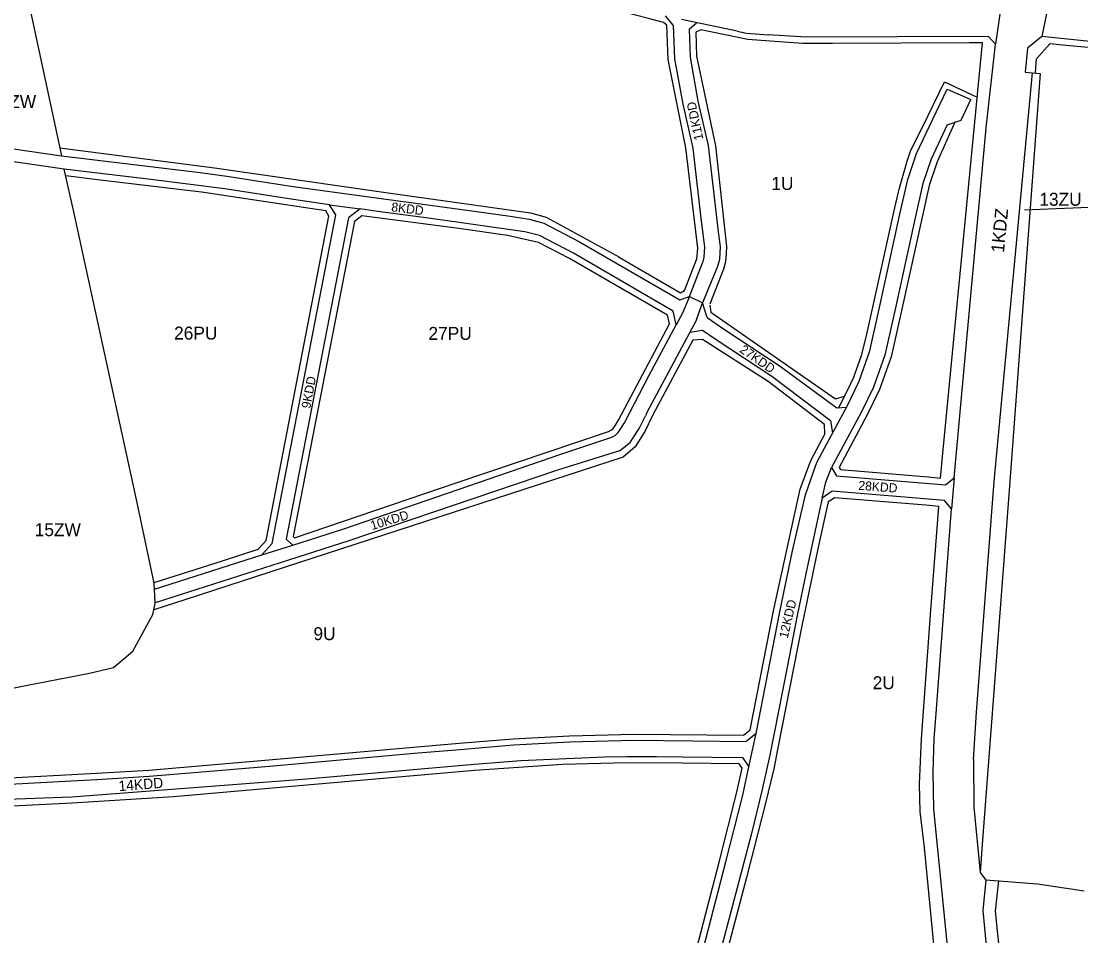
# Model space of a CAD drawing. Extents: x 7428203 to 7432868, y 5542672 to 5545406.
# Drawn here: x 7430602 to 7431420, y 5543859 to 5544564 of the extents above; entities that cross this region are included whole.
import ezdxf

# ---------------------------------------------------------------- set-up
doc = ezdxf.new("R2010")
doc.units = 0
for name, color, linetype in [('linie_rozgraniczajace', 7, 'Continuous'), ('linie_zabudowy_nieprzekraczalne', 7, 'Continuous'), ('oznaczenia_przeznaczen', 7, 'Continuous')]:
    doc.layers.add(name, color=color, linetype=linetype)

msp = doc.modelspace()

# ---------------------------------------------------------------- linework, layer by layer
at = {"layer": 'linie_rozgraniczajace'}
for p, q in [((7430604.98, 5544592.38), (7430633.38, 5544460.3)), ((7431397.08, 5544588.16), (7431389.69, 5544552.15)), ((7431105.3, 5544561.03), (7431099.31, 5544568.13)), ((7431154.56, 5544556.24), (7431111.57, 5544565.22)), ((7431357.47, 5544571.25), (7431353.84, 5544546.3)), ((7431117.44, 5544557.87), (7431123.24, 5544562.78)), ((7431154.56, 5544556.24), (7431161.78, 5544554.73)), ((7431161.78, 5544554.73), (7431178.45, 5544553.62)), ((7431207.83, 5544551.66), (7431178.45, 5544553.62)), ((7431348.46, 5544552.28), (7431207.83, 5544551.66)), ((7431353.84, 5544546.3), (7431348.46, 5544552.28)), ((7431389.69, 5544552.15), (7431378.65, 5544543.23)), ((7431346.8, 5544481.9), (7431353.84, 5544546.3)), ((7431378.65, 5544543.23), (7431376.85, 5544524.65)), ((7431388.4, 5544523.8), (7431364.07, 5544198.77)), ((7431376.85, 5544524.65), (7431388.4, 5544523.8)), ((7431305.61, 5544488.59), (7431316.53, 5544511.55)), ((7431316.53, 5544511.55), (7431334.86, 5544503.54)), ((7431327.38, 5544487.8), (7431334.86, 5544503.54)), ((7431292.99, 5544462.02), (7431305.61, 5544488.59)), ((7431316.72, 5544484.01), (7431304.14, 5544457.54)), ((7431316.72, 5544484.01), (7431327.38, 5544487.8)), ((7431321.92, 5544211.85), (7431346.8, 5544481.9)), ((7430635.44, 5544449.92), (7430571.27, 5544459.14)), ((7431286.32, 5544441.98), (7431292.99, 5544462.02)), ((7430642.68, 5544416.89), (7430635.44, 5544449.92)), ((7431304.14, 5544457.54), (7431297.89, 5544438.74)), ((7431280.12, 5544415.08), (7431286.32, 5544441.98)), ((7431297.89, 5544438.74), (7431291.83, 5544412.46)), ((7430840.14, 5544422.46), (7430863.59, 5544419.22)), ((7430691.42, 5544193.97), (7430642.68, 5544416.89)), ((7431264.97, 5544345.58), (7431280.12, 5544415.08)), ((7431291.83, 5544412.46), (7431276.68, 5544342.95)), ((7431117.86, 5544351.65), (7431127.83, 5544377.61)), ((7431139.48, 5544374.73), (7431127.74, 5544346.69)), ((7431117.86, 5544351.65), (7431127.74, 5544346.69)), ((7431123.16, 5544333.64), (7431127.74, 5544346.69)), ((7431131.44, 5544335.49), (7431127.74, 5544346.69)), ((7431256.96, 5544309.86), (7431264.97, 5544345.58)), ((7431276.68, 5544342.95), (7431268.51, 5544306.54)), ((7431123.16, 5544333.64), (7431105.78, 5544301.14)), ((7431118.1, 5544324.18), (7431127.79, 5544325.85)), ((7431248.71, 5544286.44), (7431256.96, 5544309.86)), ((7431268.51, 5544306.54), (7431259.81, 5544281.82)), ((7431105.78, 5544301.14), (7431084.94, 5544262.17)), ((7431239.85, 5544268.13), (7431248.71, 5544286.44)), ((7431259.81, 5544281.82), (7431250.54, 5544262.67)), ((7431084.94, 5544262.17), (7431083.75, 5544259.73)), ((7431216.47, 5544224.65), (7431239.85, 5544268.13)), ((7431250.54, 5544262.67), (7431227.46, 5544219.73)), ((7431231.49, 5544265.75), (7431238.91, 5544266.38)), ((7431226.58, 5544256.09), (7431228.16, 5544246.39)), ((7431063.91, 5544232.54), (7431015.88, 5544217.76)), ((7431207.33, 5544198.74), (7431215.19, 5544221.63)), ((7431215.19, 5544221.63), (7431216.47, 5544224.65)), ((7431015.88, 5544217.76), (7430854.88, 5544163.28)), ((7431227.46, 5544219.73), (7431231.25, 5544213.4)), ((7431231.25, 5544213.4), (7431315.39, 5544206.37)), ((7431315.39, 5544206.37), (7431321.92, 5544211.85)), ((7431321.92, 5544211.85), (7431320.03, 5544187.92)), ((7431197.34, 5544155.42), (7431207.33, 5544198.74)), ((7431227.87, 5544201.64), (7431220.21, 5544196.26)), ((7431314.5, 5544194.41), (7431227.87, 5544201.64)), ((7431364.07, 5544198.77), (7431343.44, 5543925.8)), ((7430704.81, 5544130.56), (7430691.42, 5544193.97)), ((7431220.21, 5544196.26), (7431218.27, 5544187.95)), ((7431320.03, 5544187.92), (7431314.5, 5544194.41)), ((7431218.27, 5544187.95), (7431207.89, 5544139.2)), ((7431308.16, 5544030.14), (7431320.03, 5544187.92)), ((7430787.97, 5544152.39), (7430811.85, 5544160.02)), ((7430854.88, 5544163.28), (7430814.89, 5544150.5)), ((7430814.89, 5544150.5), (7430705.48, 5544115.51)), ((7431187.53, 5544108.38), (7431197.34, 5544155.42)), ((7431207.89, 5544139.2), (7431200.76, 5544105.73)), ((7430705.02, 5544125.87), (7430704.81, 5544130.56)), ((7430705.48, 5544115.51), (7430705.02, 5544125.87)), ((7430703.65, 5544106.55), (7430705.51, 5544114.87)), ((7430705.51, 5544114.87), (7430705.48, 5544115.51)), ((7430688.24, 5544078.05), (7430703.65, 5544106.55)), ((7431169.21, 5544014.62), (7431187.53, 5544108.38)), ((7431200.76, 5544105.73), (7431193.28, 5544065.85)), ((7430673.38, 5544065.63), (7430688.24, 5544078.05)), ((7430654.86, 5544061.19), (7430673.38, 5544065.63)), ((7431193.28, 5544065.85), (7431179.84, 5543998.02)), ((7430607.17, 5544051.99), (7430654.86, 5544061.19)), ((7430510.83, 5544032.94), (7430607.17, 5544051.99)), ((7431306.69, 5544010.57), (7431308.16, 5544030.14)), ((7431336.87, 5543994.72), (7431339.31, 5544031)), ((7431074.8, 5544009.15), (7431025.49, 5544007.96)), ((7431120.26, 5544008.69), (7431074.8, 5544009.15)), ((7431161.3, 5544008.34), (7431120.26, 5544008.69)), ((7431169.21, 5544014.62), (7431161.3, 5544008.34)), ((7431163.66, 5543988.83), (7431169.21, 5544014.62)), ((7430940.49, 5544002.16), (7430905.41, 5543999.22)), ((7430982.03, 5544005.63), (7430940.49, 5544002.16)), ((7431025.49, 5544007.96), (7430982.03, 5544005.63)), ((7430876.98, 5543996.76), (7430793.67, 5543989.27)), ((7430905.41, 5543999.22), (7430876.98, 5543996.76)), ((7430951.57, 5543991.04), (7430987.68, 5543993.92)), ((7430987.68, 5543993.92), (7431052.25, 5543996.61)), ((7431052.25, 5543996.61), (7431069.66, 5543997.03)), ((7431069.66, 5543997.03), (7431092.3, 5543996.97)), ((7431092.3, 5543996.97), (7431112.27, 5543996.77)), ((7431112.27, 5543996.77), (7431158.71, 5543996.18)), ((7431158.71, 5543996.18), (7431163.66, 5543988.83)), ((7431179.84, 5543998.02), (7431173.73, 5543970.49)), ((7430735.33, 5543984.35), (7430700.98, 5543981.37)), ((7430793.67, 5543989.27), (7430735.33, 5543984.35)), ((7430822.44, 5543979.62), (7430951.57, 5543991.04)), ((7430631.1, 5543977.3), (7430578.76, 5543974.63)), ((7430660.59, 5543978.99), (7430631.1, 5543977.3)), ((7430641.3, 5543965.87), (7430822.44, 5543979.62)), ((7430700.98, 5543981.37), (7430660.59, 5543978.99)), ((7431173.73, 5543970.49), (7431165.55, 5543937.59)), ((7430447, 5543958.42), (7430641.3, 5543965.87)), ((7431165.55, 5543937.59), (7431123.36, 5543776.97)), ((7431343.44, 5543925.8), (7431342.05, 5543907.45)), ((7431386.19, 5543898.41), (7431346.33, 5543901.64)), ((7431422.33, 5543893.08), (7431386.19, 5543898.41))]:
    msp.add_line(p, q, dxfattribs=at)
for points in [[(7431105.3, 5544561.03), (7431106.35, 5544535.11), (7431112.57, 5544499.95), (7431120.29, 5544466.13), (7431123.22, 5544441.19), (7431126.91, 5544409.92), (7431128.31, 5544398.07), (7431129.4, 5544389.65), (7431128.94, 5544382.08), (7431127.83, 5544377.61)], [(7431117.44, 5544557.87), (7431118.31, 5544536.4), (7431124.33, 5544502.33), (7431132.13, 5544468.17), (7431140.22, 5544399.55), (7431141.45, 5544390.06), (7431140.85, 5544380.26), (7431139.48, 5544374.73)], [(7431654.46, 5543877.07), (7431672.85, 5544147.41), (7431697.38, 5544505.35), (7431680.1, 5544526.46), (7431451.66, 5544545.79), (7431389.69, 5544552.15)], [(7431339.31, 5544031), (7431352.78, 5544209), (7431382.53, 5544524.23)], [(7430569.42, 5544469.51), (7430633.38, 5544460.3), (7430740.24, 5544447.34), (7430760.86, 5544444.53), (7430811.92, 5544436.53), (7430957.31, 5544416.86), (7430981.37, 5544413.37), (7430994.17, 5544411.27), (7431005.45, 5544408.24), (7431033.05, 5544393.91), (7431110.24, 5544349.14), (7431117.86, 5544351.65), (7431112.34, 5544338.85), (7431107.55, 5544329.89), (7431105.22, 5544340.49), (7431028.24, 5544385.14), (7431002.04, 5544398.75), (7430990.73, 5544401.69), (7430916.34, 5544412.18), (7430877.04, 5544417.36), (7430863.59, 5544419.22), (7430854.75, 5544412.37), (7430806.64, 5544164.65), (7430811.85, 5544160.02), (7430851.76, 5544172.78), (7431018.42, 5544230.14), (7431057, 5544242.92), (7431058.82, 5544243.72), (7431060.71, 5544244.78), (7431062.82, 5544246.81), (7431064.84, 5544249.88), (7431067.61, 5544254.32), (7431086.71, 5544290.93), (7431105.7, 5544326.44), (7431107.55, 5544329.89)], [(7430705.02, 5544125.87), (7430787.97, 5544152.39), (7430795.78, 5544161.19), (7430844.9, 5544414.72), (7430840.14, 5544422.46), (7430810.43, 5544426.64), (7430759.42, 5544434.64), (7430702.11, 5544441.87), (7430635.44, 5544449.92)], [(7431131.44, 5544335.49), (7431144, 5544326.77), (7431187.05, 5544298.43), (7431231.49, 5544265.75)], [(7431127.79, 5544325.85), (7431138.4, 5544318.48), (7431181.34, 5544290.23), (7431226.58, 5544256.09)], [(7431063.91, 5544232.54), (7431072.1, 5544239.08), (7431078.85, 5544249.93), (7431083.75, 5544259.73)], [(7431220.21, 5544196.26), (7431223.1, 5544208.59), (7431227.46, 5544219.73)], [(7431309.1, 5543927.71), (7431306.2, 5543956.49), (7431305.78, 5543984.85), (7431306.69, 5544010.57)], [(7431336.87, 5543994.72), (7431337.06, 5543957.82), (7431342.05, 5543907.45), (7431346.33, 5543901.64), (7431344.13, 5543878.23), (7431348.52, 5543831.97), (7431390, 5543702.36), (7431390.73, 5543691.85), (7431392.19, 5543663.75), (7431392.48, 5543658.26), (7431391.71, 5543646.79), (7431385.31, 5543618.42), (7431364, 5543513.86)], [(7431094.31, 5543717.17), (7431101.48, 5543744.76), (7431145.8, 5543915.56), (7431159, 5543967.17), (7431163.66, 5543988.83)], [(7431333.87, 5543519.93), (7431356.3, 5543627.18), (7431361.52, 5543652.65), (7431362.19, 5543670.59), (7431359.03, 5543701.57), (7431327.35, 5543799.07), (7431319.67, 5543822.68), (7431309.1, 5543927.71)]]:
    msp.add_lwpolyline(points, dxfattribs=at)
at = {"layer": 'linie_zabudowy_nieprzekraczalne'}
for p, q in [((7431205.18, 5544546.83), (7431180.04, 5544548.5)), ((7431228.25, 5544546.75), (7431205.18, 5544546.83)), ((7431333.82, 5544547.21), (7431228.25, 5544546.75)), ((7431301.82, 5544491.41), (7431314.42, 5544517.15)), ((7431314.42, 5544517.15), (7431339.84, 5544505.41)), ((7431288.34, 5544463.89), (7431301.82, 5544491.41)), ((7431322.86, 5544486.63), (7431308.79, 5544455.67)), ((7431285.73, 5544456.04), (7431288.34, 5544463.89)), ((7431279.46, 5544434.49), (7431285.73, 5544456.04)), ((7431308.79, 5544455.67), (7431302.7, 5544437.38)), ((7431275.38, 5544416.79), (7431279.46, 5544434.49)), ((7431302.7, 5544437.38), (7431281.56, 5544341.86)), ((7431261.42, 5544352.78), (7431275.38, 5544416.79)), ((7431254.17, 5544320.27), (7431261.42, 5544352.78)), ((7431281.56, 5544341.86), (7431273.33, 5544305.16)), ((7431250.39, 5544306.26), (7431254.17, 5544320.27)), ((7431120.46, 5544318), (7431089.35, 5544259.81)), ((7431245.59, 5544292.62), (7431250.39, 5544306.26)), ((7431273.33, 5544305.16), (7431264.43, 5544279.89)), ((7431241.97, 5544283.99), (7431243.41, 5544286.96)), ((7431243.41, 5544286.96), (7431244.24, 5544288.79)), ((7431244.24, 5544288.79), (7431245.59, 5544292.62)), ((7431232.7, 5544265.61), (7431240.37, 5544280.68)), ((7431240.37, 5544280.68), (7431241.97, 5544283.99)), ((7431264.43, 5544279.89), (7431254.99, 5544260.4)), ((7431254.99, 5544260.4), (7431233.2, 5544219.87)), ((7431211.29, 5544225.22), (7431222.42, 5544245.99)), ((7431066.55, 5544227.91), (7430729.33, 5544117.89)), ((7431203.16, 5544203.14), (7431211.29, 5544225.22)), ((7431233.2, 5544219.87), (7431234.22, 5544218.17)), ((7431234.22, 5544218.17), (7431301.89, 5544212.52)), ((7431182.62, 5544109.36), (7431203.16, 5544203.14)), ((7431229.98, 5544196.44), (7431224.69, 5544193.29)), ((7431300.19, 5544190.78), (7431229.98, 5544196.44)), ((7431224.69, 5544193.29), (7431216.82, 5544157.13)), ((7431216.82, 5544157.13), (7431204.35, 5544097.72)), ((7430729.33, 5544117.89), (7430704.41, 5544109.95)), ((7431164.7, 5544017.42), (7431182.62, 5544109.36)), ((7431204.35, 5544097.72), (7431186.02, 5544003.48)), ((7431159.57, 5544013.36), (7431164.7, 5544017.42)), ((7430940.07, 5544007.14), (7430981.69, 5544010.62)), ((7430981.69, 5544010.62), (7431025.3, 5544012.96)), ((7431025.3, 5544012.96), (7431074.76, 5544014.15)), ((7431074.76, 5544014.15), (7431159.57, 5544013.36)), ((7430793.23, 5543994.25), (7430940.07, 5544007.14)), ((7431186.02, 5544003.48), (7431182.85, 5543987.44)), ((7430700.62, 5543986.36), (7430793.23, 5543994.25)), ((7430578.52, 5543979.63), (7430660.3, 5543983.98)), ((7430660.3, 5543983.98), (7430700.62, 5543986.36)), ((7431182.85, 5543987.44), (7431176.27, 5543959.98)), ((7431176.27, 5543959.98), (7431161.79, 5543903.59)), ((7431161.79, 5543903.59), (7431133.34, 5543795.27))]:
    msp.add_line(p, q, dxfattribs=at)
for points in [[(7431097.8, 5544563.11), (7431085.02, 5544566.28), (7431068.04, 5544570.76), (7431053.43, 5544576.37), (7431004.01, 5544606.59), (7430904.7, 5544666.36), (7430892.77, 5544671.65), (7430881.52, 5544675.43), (7430857.73, 5544679.93), (7430843.46, 5544680.67), (7430820.83, 5544678.62), (7430803.18, 5544674.25), (7430797.44, 5544672.31), (7430606.82, 5544587.15)], [(7431063.14, 5544382.37), (7431110.81, 5544354.59), (7431113.93, 5544356.36), (7431123.48, 5544380.83), (7431124.35, 5544388.98), (7431114.91, 5544466.23), (7431101.37, 5544534.57), (7431100.3, 5544560.99), (7431097.8, 5544563.11)], [(7431180.04, 5544548.5), (7431162.91, 5544549.87), (7431126.42, 5544557.33), (7431122.79, 5544555.58), (7431123.29, 5544536.94), (7431137.91, 5544467.8), (7431146.47, 5544390.23), (7431146.14, 5544384.86), (7431145.52, 5544378.33), (7431144.09, 5544372.8), (7431133.54, 5544345.78)], [(7431301.89, 5544212.52), (7431311.45, 5544211.59), (7431313.56, 5544233.49), (7431323.58, 5544337.28), (7431343.89, 5544547.26), (7431333.82, 5544547.21)], [(7431408.5, 5544545.23), (7431395.74, 5544546.5), (7431385.32, 5544534.64), (7431384.5, 5544524.49)], [(7431649.47, 5543877.41), (7431655.88, 5543974.89), (7431665.17, 5544116.21), (7431681.81, 5544351.27), (7431692.14, 5544503.86), (7431677.57, 5544521.65), (7431530.62, 5544534.23), (7431408.5, 5544545.23)], [(7430632.12, 5544466.45), (7430751.23, 5544450.89), (7430885.33, 5544431.64), (7430995.22, 5544416.16), (7431007.27, 5544412.93), (7431063.68, 5544381.92)], [(7430704.72, 5544131.02), (7430757.56, 5544147.92), (7430785.14, 5544156.73), (7430791.13, 5544163.48), (7430839.62, 5544413.76), (7430837.12, 5544417.83), (7430825.21, 5544419.51), (7430741.33, 5544432.05), (7430661.14, 5544441.78), (7430636.57, 5544444.75)], [(7431133.57, 5544344.91), (7431134.3, 5544339.6), (7431230.4, 5544272.69), (7431237.42, 5544274.88)], [(7431222.24, 5544245.67), (7431221.94, 5544253.01), (7431178.46, 5544286.14), (7431127.94, 5544318.48), (7431120.46, 5544318)], [(7431089.35, 5544259.81), (7431083.22, 5544247.49), (7431075.89, 5544235.71), (7431066.55, 5544227.91)], [(7431349.2, 5543689.58), (7431349.15, 5543699.08), (7431349.15, 5543699.08), (7431328.95, 5543762.85), (7431309.36, 5543820.12), (7431299.15, 5543926.71), (7431295.65, 5543954.49), (7431295.22, 5543975.54), (7431296.68, 5544010.53), (7431304.12, 5544109.78), (7431310.11, 5544189.63), (7431300.19, 5544190.78)], [(7431096.64, 5543746.01), (7431141.07, 5543916.56), (7431154.13, 5543968.32), (7431158.32, 5543987.8), (7431156.03, 5543991.21), (7431112.21, 5543991.77), (7431069.72, 5543992.03), (7431019.7, 5543990.63), (7430951.97, 5543986.06), (7430719.62, 5543965.92), (7430641.58, 5543960.87), (7430523.7, 5543955.12), (7430447.22, 5543953.43), (7430362.74, 5543947.9), (7430360.14, 5543944.81), (7430364.22, 5543909.88), (7430366.87, 5543843.51)], [(7431356.33, 5543901.17), (7431353.52, 5543877.68), (7431358.38, 5543832.7), (7431379.41, 5543768.24), (7431399.89, 5543704.26), (7431401.46, 5543671.4)]]:
    msp.add_lwpolyline(points, dxfattribs=at)
msp.add_lwpolyline([(7430864.99, 5544413.98), (7430859.3, 5544409.57), (7430812.09, 5544166.5), (7430813.04, 5544165.65), (7430938.54, 5544208.12), (7431055.21, 5544247.59), (7431057.7, 5544248.83), (7431058.95, 5544250.02), (7431060.63, 5544252.58), (7431063.27, 5544256.81), (7431102.27, 5544330.62), (7431100.81, 5544337.27), (7431054.52, 5544364.12), (7431025.16, 5544381.11), (7431001.35, 5544393.47), (7430977.39, 5544398.79), (7430939.91, 5544404.03)], close=True, dxfattribs=at)
at = {"layer": 'oznaczenia_przeznaczen'}
msp.add_line((7431443.25, 5544421.06), (7431376.15, 5544418.34), dxfattribs=at)

# ---------------------------------------------------------------- texts
for s, p in [('14ZW', (7430578.0633, 5544497)), ('1U', (7431180.9441, 5544433.86)), ('13ZU', (7431387.6928, 5544421.67)), ('26PU', (7430720.1328, 5544318.48)), ('27PU', (7430916.4028, 5544318.24)), ('15ZW', (7430612.5833, 5544166.85)), ('9U', (7430827.6641, 5544086.66)), ('2U', (7431259.1241, 5544048.81))]:
    msp.add_text(s, height=10, dxfattribs=at).set_placement(p)
for s, height, rotation, p in [('11KDD', 7, 101.9975752, (7431128.6063, 5544472.9856)), ('8KDD', 7, 353.1063809, (7430887.4454, 5544417.4146)), ('1KDZ', 10, 84.3788486, (7431360.3896, 5544385.091)), ('27KDD', 7, 325.2142206, (7431155.9056, 5544309.2877)), ('9KDD', 7, 79.4147776, (7430825.1825, 5544264.9168)), ('28KDD', 7, 355.6980253, (7431247.8929, 5544202.6405)), ('10KDD', 7, 16.9207371, (7430872.8829, 5544171.4811)), ('12KDD', 7, 76.8105273, (7431193.5394, 5544087.5811)), ('14KDD', 8, 4.3553887, (7430677.6157, 5543970.1488))]:
    msp.add_text(s, height=height, rotation=rotation, dxfattribs=at).set_placement(p)

doc.saveas('drawing.dxf')
